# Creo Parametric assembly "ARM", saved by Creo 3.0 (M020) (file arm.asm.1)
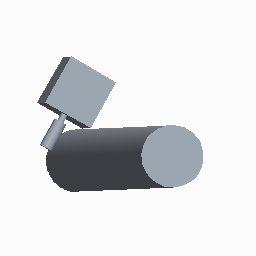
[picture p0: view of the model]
Units: millimeter Newton Second (mmNs); MM, TONNE, SECS

Created from: MMNS_ASM_DESIGN.ASM

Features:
  1. datum plane "ASM_RIGHT"
  2. datum plane "ASM_TOP"
  3. datum plane "ASM_FRONT"
  4. coordinate system
  5. component "PIPE"
  6. component "ARM_MOTOR"

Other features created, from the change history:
  component "ARM_MOTOR.PRT"
  component "PIPE.PRT" (2 times)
